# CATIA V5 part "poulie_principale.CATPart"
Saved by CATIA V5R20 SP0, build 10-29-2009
Part number: poulie_principale
Bounding box of the stored display mesh (mm): x 575.778 to 635.778, y 167.112 to 327.101, z -79.994 to 79.994
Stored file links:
  D:\Dropbox\MMS_GR3\bfoltzer\CFAO_bfoltzer\poulie_principale.CATPart
  D:\ecole\thinkmotion\Eolienne.CATProduct
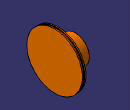
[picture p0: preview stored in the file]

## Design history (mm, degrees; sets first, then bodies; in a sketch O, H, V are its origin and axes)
Set1
  Plane1: linked copy from another document
  Point1 to Point6: linked copy from another document
  Line1: linked copy from another document
Body1 (main body)
  Sketch1 on Plane1, origin (0, 330.1148, -190.9082), H (-1, 0, 0), V (0, 0.3987, -0.9171)
    point P1 (-575.7782, -208.1738)
    line L1 (-575.7782, -208.1738) -> (-625.7782, -208.1738)
    line L2 (-625.7782, -208.1738) -> (-625.7782, -248.1738)
    line L3 (-625.7782, -248.1738) -> (-575.7782, -248.1738)
    line L4 (-575.7782, -248.1738) -> (-575.7782, -208.1738)
    point P2 (-625.7782, -208.1738)
    point P3 (-625.7782, -248.1738)
    reference projected point E1 (-625.7782, -248.1738) from Point1
    reference projected point E2 (-575.7782, -208.1738) from Point2
    point P5 (-635.7782, -208.1738)
    line L5 (-635.7782, -208.1738) -> (-625.7782, -208.1738)
    line L6 (-625.7782, -208.1738) -> (-625.7782, -288.1738)
    line L7 (-625.7782, -288.1738) -> (-635.7782, -288.1738)
    line L8 (-635.7782, -288.1738) -> (-635.7782, -208.1738)
    point P6 (-625.7782, -208.1738)
    point P7 (-625.7782, -288.1738)
    reference projected point E3 (-625.7782, -288.1738) from Point3
    reference projected point E4 (-635.7782, -208.1738) from Point4
    horizontal: L1 H, L3 H, L5 H, L7 H
    vertical: L2 V, L4 V, L6 V, L8 V
    coincidence: P3 E1, P1 E2, P7 E3, P5 E4, P2 P6
  Shaft1: profile Sketch1, axis Line1, angle 360
  Sketch2 on Plane1, origin (0, 330.1148, -190.9082), H (-1, 0, 0), V (0, 0.3987, -0.9171)
    point P1 (-632.2782, -287.1738)
    line L1 (-632.2782, -287.1738) -> (-629.2782, -287.1738)
    line L2 (-629.2782, -287.1738) -> (-629.2782, -288.1738)
    line L3 (-629.2782, -288.1738) -> (-632.2782, -288.1738)
    line L4 (-632.2782, -288.1738) -> (-632.2782, -287.1738)
    point P3 (-629.2782, -288.1738)
    reference projected point E1 (-632.2782, -287.1738) from Point5
    reference projected point E2 (-629.2782, -288.1738) from Point6
    horizontal: L1 H, L3 H
    vertical: L2 V, L4 V
    coincidence: P1 E1, P3 E2
  Groove1: profile Sketch2, axis Line1, angle 360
